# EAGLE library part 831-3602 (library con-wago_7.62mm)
Serie 831, Stiftleiste (für Leiterplatten) mit geraden Einlötstiften / Series 831, Male header (for PCBs) with straight solder pins Polzahl / Pole No.: 2 Bemessungsspannung / Rated Voltage: 630 V Nennstrom / Nominal Current: 41 A Lötstiftlänge: / Solder Pin Length: 4 mm Farbe / Color: lichtgrau / light gray Stand: 01.01.2012. Die jeweils aktuellen Daten zu diesem Artikel finden Sie in unserem Produktkatalog, den Sie unter www.wago.com einsehen können. As of: 01/01/2012. Please find the newest data for this article in our product catalogue, which can be viewed under www.wago.com.
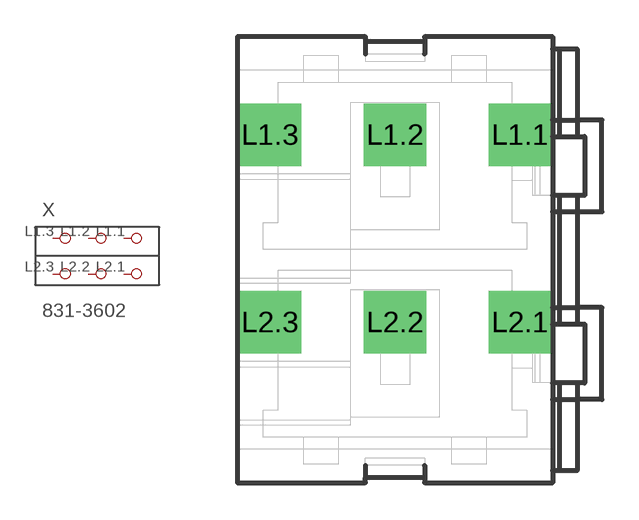
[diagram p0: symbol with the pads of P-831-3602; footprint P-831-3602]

Designator prefix X

## 831-3602  [P-831-3602]
L1.1  P1.1
L1.2  P1.2
L1.3  P1.3
L2.1  P2.1
L2.2  P2.2
L2.3  P2.3

## Footprint P-831-3602 (pad centres in mm)
drill 1.7 square: L1.1 4.08,5.08; L1.2 -1,5.08; L1.3 -6.08,5.08; L2.1 4.08,-2.54; L2.2 -1,-2.54; L2.3 -6.08,-2.54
